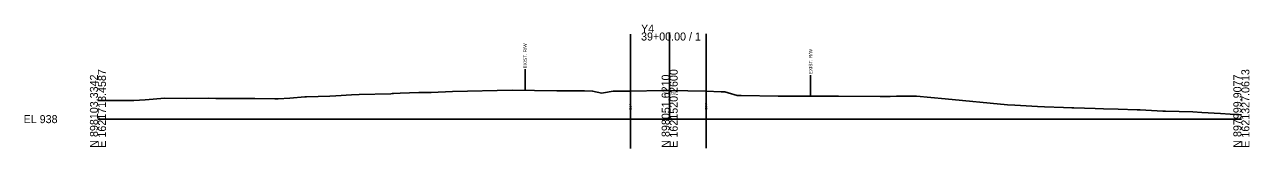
# Model space of a CAD drawing. Extents: x -329 to 3203, y 2487 to 9033.
# Drawn here: x -25.7 to 402.8, y 8989.7 to 9033.1 of the extents above; entities that cross this region are included whole.
import ezdxf

# ---------------------------------------------------------------- set-up
doc = ezdxf.new("R2010")
doc.units = 0
for name, color, linetype in [('Exist Cross Section Cell', 7, 'Continuous'), ('Exist XS Center Line Elevation Label', 7, 'Continuous'), ('Exist XS Ground Line', 7, 'Continuous'), ('Old_Level_10', 7, 'Continuous'), ('Scratch_Level_4', 7, 'Continuous')]:
    doc.layers.add(name, color=color, linetype=linetype)

msp = doc.modelspace()

# ---------------------------------------------------------------- linework, layer by layer
at = {"layer": 'Exist Cross Section Cell'}
for p, q in [((200, 9000), (200, 9030.3)), ((0, 9000), (200, 9000)), ((200, 9000), (400, 9000))]:
    msp.add_line(p, q, dxfattribs=at)
at = {"layer": 'Exist XS Ground Line'}
msp.add_lwpolyline([(0, 9006.49), (1.31, 9006.55), (3.58, 9006.55), (12.58, 9006.49), (16.49, 9006.78), (23.35, 9007.36), (30.87, 9007.25), (38.52, 9007.28), (41.22, 9007.25), (46.68, 9007.25), (51.57, 9007.22), (54.85, 9007.21), (61.93, 9007.08), (63.02, 9007.14), (67.1, 9007.38), (72.36, 9007.77), (72.99, 9007.8), (81.17, 9008.06), (83.21, 9008.12), (88.69, 9008.48), (91.33, 9008.63), (102.45, 9008.89), (102.96, 9008.91), (103.34, 9008.91), (105.77, 9009.03), (112.22, 9009.31), (116.58, 9009.37), (124.04, 9009.66), (144.86, 9010.1), (160.53, 9009.85), (163.55, 9009.89), (166.26, 9009.9), (170.21, 9009.9), (173.04, 9009.83), (176.29, 9009.09), (176.8, 9009.17), (180.2, 9009.74), (181.07, 9009.78), (184.43, 9009.78), (185.99, 9009.73), (186.34, 9009.73), (197.64, 9009.99), (199.58, 9010.04), (200, 9010.03), (212.73, 9009.84), (218.02, 9009.59), (219.34, 9009.52), (220.45, 9009.22), (223.67, 9008.3), (225.06, 9008.27), (237.92, 9008.09), (242.68, 9008.06), (248.27, 9008.01), (250.85, 9008.04), (258.62, 9008.04), (259.02, 9008.04), (273.59, 9007.91), (276.06, 9007.95), (277.11, 9007.94), (279.37, 9008.04), (281.82, 9008.04), (286.37, 9008.04), (296.32, 9007.11), (318.19, 9005.01), (320.74, 9004.84), (328.63, 9004.43), (331.09, 9004.28), (337.83, 9004.08), (340.68, 9004.01), (341.44, 9003.98), (348.85, 9003.77), (351.8, 9003.66), (356.9, 9003.47), (363.51, 9003.25), (364.54, 9003.25), (372.47, 9002.83), (372.92, 9002.82), (373.46, 9002.78), (383.07, 9002.51), (386.21, 9002.27), (392.66, 9001.93), (396.09, 9001.69), (400, 9001.48)], dxfattribs=at)
at = {"layer": 'Old_Level_10'}
for p, q in [((149.41, 9017.43), (149.41, 9010.03)), ((249.28, 9015.42), (249.28, 9008.02)), ((186.34, 9009.73), (186.34, 9005.63)), ((212.73, 9009.84), (212.73, 9005.74))]:
    msp.add_line(p, q, dxfattribs=at)
at = {"layer": 'Scratch_Level_4'}
for p, q in [((186.34, 9029.73), (186.34, 8989.73)), ((212.73, 9029.84), (212.73, 8989.84))]:
    msp.add_line(p, q, dxfattribs=at)

# ---------------------------------------------------------------- texts
at = {"layer": 'Exist Cross Section Cell'}
for s, p in [('Y4', (190, 9030.3)), ('39+00.00 / 1', (190, 9027.5)), ('EL 938', (-26, 8998.6))]:
    msp.add_text(s, height=2.8, dxfattribs=at).set_placement(p)
for s, p in [('E 1621713.4587', (2.8, 8990)), ('E 1621520.2600', (202.8, 8990)), ('E 1621327.0613', (402.8, 8990)), ('N 898103.3342', (0, 8990)), ('N 898051.6210', (200, 8990)), ('N 897999.9077', (400, 8990))]:
    msp.add_text(s, height=2.8, rotation=90, dxfattribs=at).set_placement(p)
at = {"layer": 'Exist XS Center Line Elevation Label'}
msp.add_text('948.03', height=1, dxfattribs=at).set_placement((197.88, 9008.53))
at = {"layer": 'Old_Level_10'}
for s, height, p in [('EXIST. R/W', 1.181, (150, 9017.73)), ('EXIST. R/W', 1.181, (249.87, 9015.72)), ('EOP', 0.787, (186.73, 9003.23)), ('EOP', 0.787, (213.12, 9003.34))]:
    msp.add_text(s, height=height, rotation=90, dxfattribs=at).set_placement(p)

doc.saveas('drawing.dxf')
